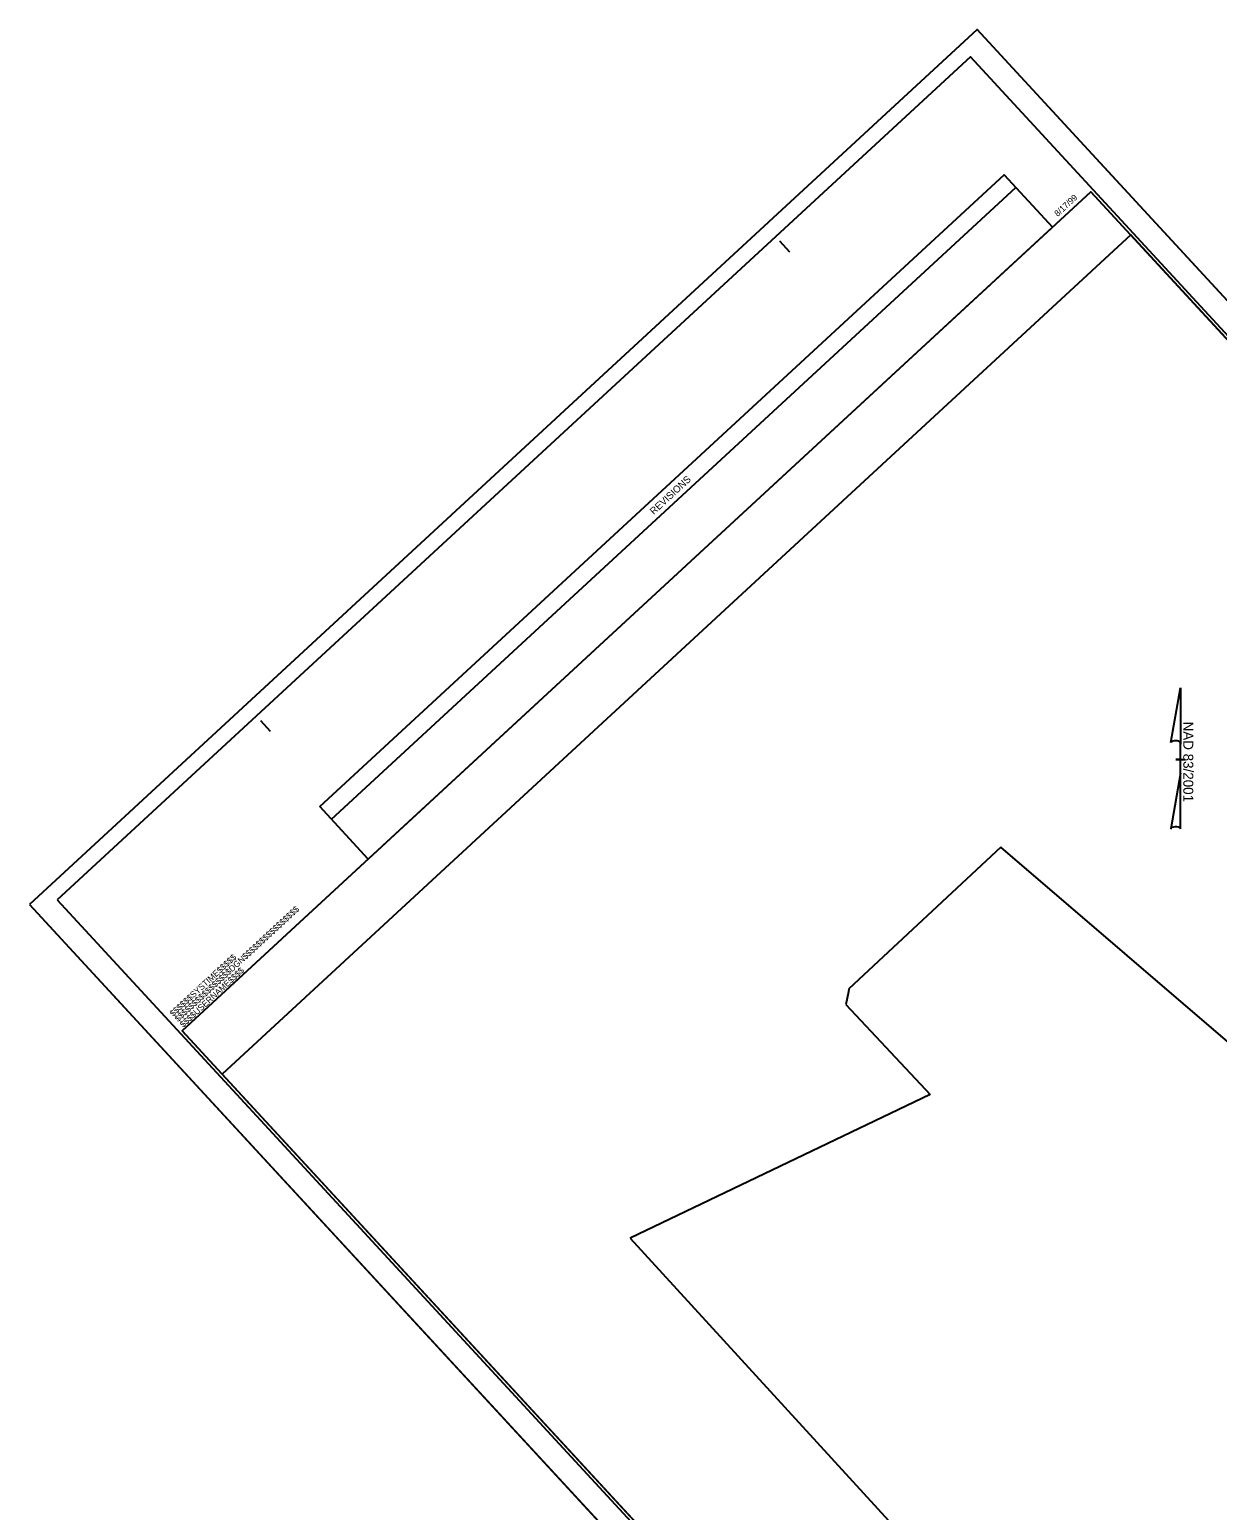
# Model space of a CAD drawing. Extents: x 1702855 to 1704859, y 793650 to 795630.
# Drawn here: x 1702855 to 1703864, y 794373 to 795630 of the extents above; entities that cross this region are included whole.
import ezdxf

# ---------------------------------------------------------------- set-up
doc = ezdxf.new("R2010")
doc.units = 0
for name, color, linetype in [('Prop North Arrow NAD83 for Plan Sheets CELL', 7, 'Continuous'), ('Sheet Block Revision CELL', 7, 'Continuous'), ('Sheet Clip Boundary CELL', 7, 'Continuous'), ('Sheet Cutting Line CELL', 7, 'Continuous'), ('Sheet Layout Plan Border', 7, 'Continuous'), ('Sheet Plan CELL', 7, 'Continuous'), ('Sheet Plan Layout CELL', 7, 'Continuous'), ('Sheet Plot Border Inside CELL', 7, 'Continuous'), ('Sheet Plot Border Outside CELL', 7, 'Continuous')]:
    doc.layers.add(name, color=color, linetype=linetype)

msp = doc.modelspace()

# ---------------------------------------------------------------- linework, layer by layer
at = {"layer": 'Prop North Arrow NAD83 for Plan Sheets CELL'}
for p, q in [((1703824.1, 795025.1), (1703832.3, 795071.5)), ((1703832.3, 795071.5), (1703832.3, 795071.5)), ((1703832.3, 795071.5), (1703832.3, 795071.5)), ((1703832.3, 795071.5), (1703832.3, 795023.7)), ((1703832.3, 794998.9), (1703832.3, 795025.1)), ((1703832.3, 795023.7), (1703832.3, 795025)), ((1703831.9, 795010.5), (1703828.3, 795010.5)), ((1703828.3, 795010.5), (1703828.3, 795010.5)), ((1703828.4, 795010.5), (1703836.4, 795010.5)), ((1703832.3, 794998.9), (1703824, 794951.6)), ((1703832.4, 794951.8), (1703832.3, 794998.9))]:
    msp.add_line(p, q, dxfattribs=at)
for centre, start_param, end_param in [((1703828.2, 795024.6), 0.216388, 2.908219), ((1703828.2, 794951.5), 0.201328, 3.141593)]:
    msp.add_ellipse(centre, major_axis=(4.23, -0.03), ratio=0.461098, start_param=start_param, end_param=end_param, dxfattribs=at)
at = {"layer": 'Sheet Block Revision CELL'}
msp.add_line((1703111.4, 794959.9), (1703692.4, 795496.2), dxfattribs=at)
msp.add_lwpolyline([(1703101.5, 794970.6), (1703682.5, 795506.9), (1703723.6, 795462.4), (1703142.6, 794926.1)], close=True, dxfattribs=at)
at = {"layer": 'Sheet Clip Boundary CELL'}
for p, q in [((1703679.9, 794936.1), (1703550.7, 794815.9)), ((1703941.8, 794711.4), (1703679.9, 794936.1)), ((1703550.3, 794813.5), (1703548.3, 794802.6)), ((1703550.7, 794815.9), (1703550.3, 794813.5)), ((1703548.3, 794802.6), (1703619.7, 794726.3)), ((1703619.7, 794726.3), (1703365.1, 794604.4)), ((1703365.1, 794604.4), (1703679.4, 794261.1))]:
    msp.add_line(p, q, dxfattribs=at)
msp.add_lwpolyline([(1703018.5, 794743.6), (1703968.1, 793714.8), (1704584.3, 794283.6), (1704455.9, 794422.7), (1704611.3, 794566.1), (1703790.1, 795455.8)], close=True, dxfattribs=at)
at = {"layer": 'Sheet Cutting Line CELL'}
for p, q in [((1703659.7, 795630.1), (1702855.1, 794887.4)), ((1704801.6, 794393), (1703659.7, 795630.1)), ((1702855.1, 794887.4), (1703997, 793650.3))]:
    msp.add_line(p, q, dxfattribs=at)
at = {"layer": 'Sheet Layout Plan Border'}
msp.add_lwpolyline([(1703018.5, 794743.6), (1703968.1, 793714.8), (1704584.3, 794283.6), (1704455.9, 794422.7), (1704611.3, 794566.1), (1703790.1, 795455.8)], close=True, dxfattribs=at)
at = {"layer": 'Sheet Plan CELL'}
for p, q in [((1703756.2, 795492.5), (1703756.2, 795492.5)), ((1703491.9, 795450.7), (1703500.4, 795441.5)), ((1703051.1, 795043.7), (1703059.5, 795034.5)), ((1702984.6, 794780.3), (1702984.6, 794780.3))]:
    msp.add_line(p, q, dxfattribs=at)
for points in [[(1704773.6, 794390.3), (1703756.2, 795492.5), (1702984.6, 794780.3), (1704002, 793678.1)], [(1702984.6, 794780.3), (1703756.1, 795492.5), (1704637.9, 794537.3), (1704527.6, 794435.5), (1704663.3, 794288.5), (1704002, 793678.1)]]:
    msp.add_lwpolyline(points, close=True, dxfattribs=at)
at = {"layer": 'Sheet Plan Layout CELL'}
msp.add_lwpolyline([(1703756.1, 795492.5), (1702984.6, 794780.3), (1704002, 793678.1), (1704618.2, 794246.8), (1704455.9, 794422.7), (1704611.3, 794566.1)], close=True, dxfattribs=at)
at = {"layer": 'Sheet Plot Border Inside CELL'}
msp.add_lwpolyline([(1702878.6, 794891.4), (1704008.7, 793667.2), (1704783.9, 794382.8), (1703653.9, 795607)], close=True, dxfattribs=at)
at = {"layer": 'Sheet Plot Border Outside CELL'}
msp.add_lwpolyline([(1702855.1, 794887.4), (1703997, 793650.3), (1704801.6, 794393), (1703659.7, 795630.1)], close=True, dxfattribs=at)

# ---------------------------------------------------------------- texts
at = {"layer": 'Prop North Arrow NAD83 for Plan Sheets CELL'}
msp.add_text('NAD 83/2001', height=8.5, rotation=270, dxfattribs=at).set_placement((1703834.7, 795042.7))
at = {"layer": 'Sheet Block Revision CELL'}
msp.add_text('REVISIONS', height=6, rotation=42.7091, dxfattribs=at).set_placement((1703385.1, 795218))
at = {"layer": 'Sheet Plan CELL'}
for s, p in [('8/17/99', (1703728.1, 795471)), ('$$$$$$$$$$$$$$$$DGN$$$$$$$$$$$$$$$$', (1702981.2, 794787.5)), ('$$$$$$SYSTIME$$$$$', (1702977, 794792)), ('$$$$USERNAME$$$$', (1702985.6, 794782.7))]:
    msp.add_text(s, height=5.25, rotation=42.7091, dxfattribs=at).set_placement(p)

doc.saveas('drawing.dxf')
